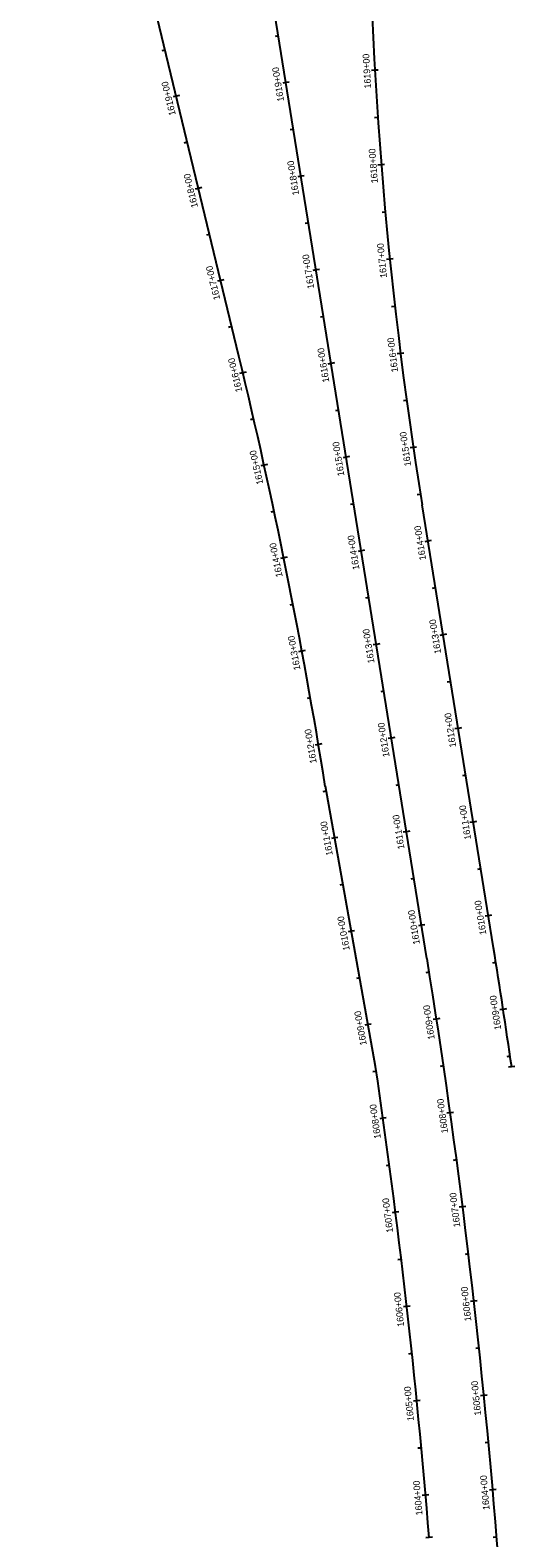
# Model space of a CAD drawing. Extents: x 596008 to 607538, y 326212 to 405053.
# Drawn here: x 602716 to 603232, y 384685 to 386274 of the extents above; entities that cross this region are included whole.
import ezdxf

# ---------------------------------------------------------------- set-up
doc = ezdxf.new("R2010")
doc.units = 0
doc.layers.add('P_ALI_200', color=7, linetype='Continuous')
doc.layers.add('P_ALI_200_Sta', color=7, linetype='Continuous')

msp = doc.modelspace()

# ---------------------------------------------------------------- linework, layer by layer
at = {"layer": 'P_ALI_200'}
for points in [[(602936.1, 385930.4), (602715.8, 386843.1)], [(603134.4, 385295.3), (602911, 386682.2)], [(603204.5, 385306.6), (603129.3, 385773.8)], [(603080.1, 385181.6), (603027.2, 385477)]]:
    msp.add_lwpolyline(points, dxfattribs=at)
for centre, radius, start, end in [((607572, 386489.4), 4500, 179.9732, 189.1499), ((597103.5, 384522.8), 6000, 9.14994, 13.56761), ((595536.1, 384071.4), 7767.3, 8.21466, 9.14994), ((595536.1, 384071.4), 7696.3, 359.95198, 9.14994), ((595536.1, 384071.4), 7625.3, 4.61463, 8.37157)]:
    msp.add_arc(centre, radius, start, end, dxfattribs=at)
at = {"layer": 'P_ALI_200_Sta'}
for points in [[(602977.7, 386268.3), (602974.2, 386267.7)], [(602858.2, 386253.2), (602854.8, 386252.4)], [(603079.4, 386232), (603075.9, 386231.8)], [(603082.9, 386232.2), (603079.4, 386232)], [(603079.4, 386232), (603079.4, 386232)], [(602985.6, 386218.9), (602982.2, 386218.4)], [(602989.1, 386219.5), (602985.6, 386218.9)], [(602985.6, 386218.9), (602985.6, 386218.9)], [(602869.9, 386204.6), (602866.5, 386203.8)], [(602873.3, 386205.4), (602869.9, 386204.6)], [(602869.9, 386204.6), (602869.9, 386204.6)], [(603082.5, 386182.1), (603079, 386181.9)], [(602993.6, 386169.5), (602990.1, 386169)], [(602881.6, 386156), (602878.2, 386155.2)], [(603086.2, 386132.3), (603082.7, 386132)], [(603089.7, 386132.5), (603086.2, 386132.3)], [(603086.2, 386132.3), (603086.2, 386132.3)], [(603001.5, 386120.2), (602998.1, 386119.6)], [(603005, 386120.7), (603001.5, 386120.2)], [(603001.5, 386120.2), (603001.5, 386120.2)], [(602893.4, 386107.4), (602890, 386106.6)], [(602896.8, 386108.2), (602893.4, 386107.4)], [(602893.4, 386107.4), (602893.4, 386107.4)], [(603090.4, 386082.4), (603087, 386082.1)], [(603009.5, 386070.8), (603006, 386070.3)], [(602905.1, 386058.8), (602901.7, 386058)], [(603095.2, 386032.7), (603091.8, 386032.3)], [(603098.7, 386033), (603095.2, 386032.7)], [(603095.2, 386032.7), (603095.2, 386032.7)], [(603017.5, 386021.5), (603014, 386020.9)], [(603020.9, 386022), (603017.5, 386021.5)], [(603017.5, 386021.5), (603017.5, 386021.5)], [(602916.8, 386010.2), (602913.4, 386009.4)], [(602920.2, 386011), (602916.8, 386010.2)], [(602916.8, 386010.2), (602916.8, 386010.2)], [(603025.4, 385972.1), (603021.9, 385971.5)], [(603100.6, 385983), (603097.1, 385982.6)], [(602928.5, 385961.6), (602925.1, 385960.8)], [(603033.4, 385922.7), (603029.9, 385922.2)], [(603036.8, 385923.3), (603033.4, 385922.7)], [(603033.4, 385922.7), (603033.4, 385922.7)], [(603106.5, 385933.3), (603103, 385932.9)], [(603110, 385933.7), (603106.5, 385933.3)], [(603106.5, 385933.3), (603106.5, 385933.3)], [(602940.3, 385913), (602936.8, 385912.2)], [(602943.7, 385913.8), (602940.3, 385913)], [(602940.3, 385913), (602940.3, 385913)], [(603041.3, 385873.4), (603037.8, 385872.8)], [(603112.9, 385883.7), (603109.5, 385883.3)], [(602951.6, 385864.3), (602948.2, 385863.5)], [(603119.9, 385834.2), (603116.5, 385833.7)], [(603123.4, 385834.7), (603119.9, 385834.2)], [(603119.9, 385834.2), (603119.9, 385834.2)], [(602962.6, 385815.5), (602959.2, 385814.7)], [(602966, 385816.3), (602962.6, 385815.5)], [(602962.6, 385815.5), (602962.6, 385815.5)], [(603049.3, 385824), (603045.8, 385823.4)], [(603052.7, 385824.6), (603049.3, 385824)], [(603049.3, 385824), (603049.3, 385824)], [(603127.5, 385784.8), (603124, 385784.2)], [(602973.2, 385766.6), (602969.8, 385765.9)], [(603057.2, 385774.6), (603053.8, 385774.1)], [(603135.4, 385735.4), (603132, 385734.9)], [(603138.9, 385736), (603135.4, 385735.4)], [(603135.4, 385735.4), (603135.4, 385735.4)], [(602983.3, 385717.7), (602979.9, 385717)], [(602986.8, 385718.4), (602983.3, 385717.7)], [(602983.3, 385717.7), (602983.3, 385717.7)], [(603065.2, 385725.3), (603061.7, 385724.7)], [(603068.6, 385725.8), (603065.2, 385725.3)], [(603065.2, 385725.3), (603065.2, 385725.3)], [(603143.4, 385686.1), (603139.9, 385685.5)], [(602993.1, 385668.6), (602989.7, 385668)], [(603073.1, 385675.9), (603069.7, 385675.4)], [(603151.3, 385636.7), (603147.9, 385636.1)], [(603154.8, 385637.3), (603151.3, 385636.7)], [(603151.3, 385636.7), (603151.3, 385636.7)], [(603002.4, 385619.5), (602999, 385618.9)], [(603005.9, 385620.2), (603002.4, 385619.5)], [(603002.4, 385619.5), (603002.4, 385619.5)], [(603081.1, 385626.5), (603077.6, 385626)], [(603084.5, 385627.1), (603081.1, 385626.5)], [(603081.1, 385626.5), (603081.1, 385626.5)], [(603159.3, 385587.3), (603155.8, 385586.8)], [(603089, 385577.2), (603085.6, 385576.6)], [(603011.4, 385570.3), (603007.9, 385569.7)], [(603097, 385527.8), (603093.5, 385527.3)], [(603100.4, 385528.4), (603097, 385527.8)], [(603097, 385527.8), (603097, 385527.8)], [(603167.2, 385538), (603163.8, 385537.4)], [(603170.7, 385538.5), (603167.2, 385538)], [(603167.2, 385538), (603167.2, 385538)], [(603019.9, 385521.1), (603016.4, 385520.5)], [(603023.3, 385521.6), (603019.9, 385521.1)], [(603019.9, 385521.1), (603019.9, 385521.1)], [(603104.9, 385478.5), (603101.5, 385477.9)], [(603175.2, 385488.6), (603171.7, 385488)], [(603028.1, 385471.7), (603024.7, 385471.1)], [(603112.9, 385429.1), (603109.4, 385428.5)], [(603116.3, 385429.6), (603112.9, 385429.1)], [(603112.9, 385429.1), (603112.9, 385429.1)], [(603183.1, 385439.2), (603179.7, 385438.7)], [(603186.6, 385439.8), (603183.1, 385439.2)], [(603183.1, 385439.2), (603183.1, 385439.2)], [(603036.9, 385422.5), (603033.5, 385421.9)], [(603040.4, 385423.1), (603036.9, 385422.5)], [(603036.9, 385422.5), (603036.9, 385422.5)], [(603120.8, 385379.7), (603117.4, 385379.2)], [(603191.1, 385389.9), (603187.6, 385389.3)], [(603045.7, 385373.3), (603042.3, 385372.7)], [(603199, 385340.5), (603195.6, 385340)], [(603202.5, 385341.1), (603199, 385340.5)], [(603199, 385340.5), (603199, 385340.5)], [(603054.6, 385324.1), (603051.1, 385323.5)], [(603058, 385324.7), (603054.6, 385324.1)], [(603054.6, 385324.1), (603054.6, 385324.1)], [(603128.8, 385330.4), (603125.3, 385329.8)], [(603132.2, 385330.9), (603128.8, 385330.4)], [(603128.8, 385330.4), (603128.8, 385330.4)], [(603207, 385291.1), (603203.5, 385290.6)], [(603063.4, 385274.9), (603059.9, 385274.2)], [(603136.7, 385281), (603133.2, 385280.4)], [(603214.7, 385241.7), (603211.2, 385241.2)], [(603218.1, 385242.3), (603214.7, 385241.7)], [(603214.7, 385241.7), (603214.7, 385241.7)], [(603072.2, 385225.7), (603068.8, 385225)], [(603075.6, 385226.3), (603072.2, 385225.7)], [(603072.2, 385225.7), (603072.2, 385225.7)], [(603144.4, 385231.6), (603140.9, 385231.1)], [(603147.9, 385232.1), (603144.4, 385231.6)], [(603144.4, 385231.6), (603144.4, 385231.6)], [(603222, 385192.3), (603218.6, 385191.8)], [(603080.9, 385176.4), (603077.4, 385175.9)], [(603151.8, 385182.1), (603148.3, 385181.6)], [(603223.7, 385181.2), (603220.2, 385180.7)], [(603227.1, 385181.7), (603223.7, 385181.2)], [(603223.7, 385181.2), (603223.7, 385181.2)], [(603087.9, 385126.9), (603084.5, 385126.4)], [(603091.4, 385127.4), (603087.9, 385126.9)], [(603087.9, 385126.9), (603087.9, 385126.9)], [(603158.8, 385132.6), (603155.4, 385132.2)], [(603162.3, 385133.1), (603158.8, 385132.6)], [(603158.8, 385132.6), (603158.8, 385132.6)], [(603165.6, 385083.1), (603162.1, 385082.6)], [(603094.7, 385077.4), (603091.2, 385076.9)], [(603172, 385033.5), (603168.5, 385033.1)], [(603175.4, 385033.9), (603172, 385033.5)], [(603172, 385033.5), (603172, 385033.5)], [(603101.1, 385027.8), (603097.7, 385027.3)], [(603104.6, 385028.2), (603101.1, 385027.8)], [(603101.1, 385027.8), (603101.1, 385027.8)], [(603178.1, 384983.9), (603174.6, 384983.5)], [(603107.2, 384978.2), (603103.8, 384977.7)], [(603187.3, 384934.6), (603183.8, 384934.2)], [(603113, 384928.5), (603109.5, 384928.1)], [(603116.5, 384928.9), (603113, 384928.5)], [(603113, 384928.5), (603113, 384928.5)], [(603183.8, 384934.2), (603180.4, 384933.8)], [(603183.8, 384934.2), (603183.8, 384934.2)], [(603118.5, 384878.8), (603115, 384878.4)], [(603189.3, 384884.5), (603185.8, 384884.1)], [(603123.6, 384829.1), (603120.1, 384828.7)], [(603127.1, 384829.4), (603123.6, 384829.1)], [(603123.6, 384829.1), (603123.6, 384829.1)], [(603194.4, 384834.8), (603190.9, 384834.4)], [(603197.9, 384835.1), (603194.4, 384834.8)], [(603194.4, 384834.8), (603194.4, 384834.8)], [(603128.4, 384779.3), (603124.9, 384779)], [(603199.2, 384785), (603195.7, 384784.7)], [(603132.9, 384729.5), (603129.4, 384729.2)], [(603136.4, 384729.8), (603132.9, 384729.5)], [(603132.9, 384729.5), (603132.9, 384729.5)], [(603203.7, 384735.2), (603200.2, 384734.9)], [(603207.2, 384735.5), (603203.7, 384735.2)], [(603203.7, 384735.2), (603203.7, 384735.2)], [(603136.6, 384684.9), (603133.1, 384684.6)], [(603140.1, 384685.2), (603136.6, 384684.9)], [(603136.6, 384684.9), (603136.6, 384684.9)], [(603207.8, 384685.4), (603204.3, 384685.1)]]:
    msp.add_lwpolyline(points, dxfattribs=at)

# ---------------------------------------------------------------- texts
for s, height, rotation, p in [('1619+00', 7, 93.2784, (603075.5, 386212.9)), ('1619+00', 7, 99.1499, (602983.7, 386199.5)), ('1619+00', 7, 103.5676, (602869.5, 386185.1)), ('1618+00', 7, 94.5517, (603082.7, 386113.1)), ('1618+00', 7, 99.1499, (602999.6, 386100.8)), ('1618+00', 7, 103.5676, (602892.9, 386087.9)), ('1617+00', 7, 95.8249, (603092.2, 386013.4)), ('1617+00', 7, 99.1499, (603015.5, 386002.1)), ('1617+00', 7, 103.5676, (602916.4, 385990.7)), ('1616+00', 7, 99.1499, (603031.4, 385903.4)), ('1616+00', 7, 97.0982, (603103.9, 385914)), ('1616+00', 7, 103.3964, (602939.7, 385893.5)), ('1615+00', 7, 98.3714, (603117.7, 385814.9)), ('1615+00', 7, 102.4414, (602961.8, 385796)), ('1615+00', 7, 99.1499, (603047.3, 385804.6)), ('1614+00', 7, 99.1499, (603133.5, 385716)), ('1614+00', 7, 101.4865, (602982.2, 385698.2)), ('1614+00', 7, 99.1499, (603063.2, 385705.9)), ('1613+00', 7, 99.1499, (603149.4, 385617.3)), ('1613+00', 7, 100.5316, (603001, 385600.1)), ('1613+00', 7, 99.1499, (603079.1, 385607.2)), ('1612+00', 7, 99.1499, (603095, 385508.4)), ('1612+00', 7, 99.1499, (603165.3, 385518.6)), ('1612+00', 7, 99.5767, (603018.1, 385501.7)), ('1611+00', 7, 99.1499, (603110.7, 385411.2)), ('1611+00', 7, 99.1499, (603181, 385421.3)), ('1611+00', 7, 100.1614, (603035.1, 385404.5)), ('1610+00', 7, 99.1499, (603197.1, 385320.9)), ('1610+00', 7, 100.1614, (603053, 385304.4)), ('1610+00', 7, 99.1499, (603126.9, 385310.8)), ('1609+00', 7, 98.6658, (603212.8, 385220.7)), ('1609+00', 7, 100.1614, (603070.9, 385204.5)), ('1609+00', 7, 98.67, (603142.6, 385210.5)), ('1608+39', 0.0000000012, 98.2147, (603218.7, 385180.5)), ('1608+00', 7, 97.9563, (603085.8, 385105.9)), ('1608+00', 7, 97.9255, (603156.7, 385111.6)), ('1607+00', 7, 97.181, (603169.6, 385012.5)), ('1607+00', 7, 97.2049, (603098.7, 385006.8)), ('1606+00', 7, 96.4535, (603110.4, 384907.5)), ('1606+00', 7, 96.4366, (603181.2, 384913.3)), ('1605+00', 7, 95.7021, (603120.7, 384808.1)), ('1605+00', 7, 95.6921, (603191.5, 384813.9)), ('1604+00', 7, 94.9507, (603129.7, 384708.6)), ('1604+00', 7, 94.9477, (603200.5, 384714.3))]:
    msp.add_text(s, height=height, rotation=rotation, dxfattribs=at).set_placement(p)

doc.saveas('drawing.dxf')
